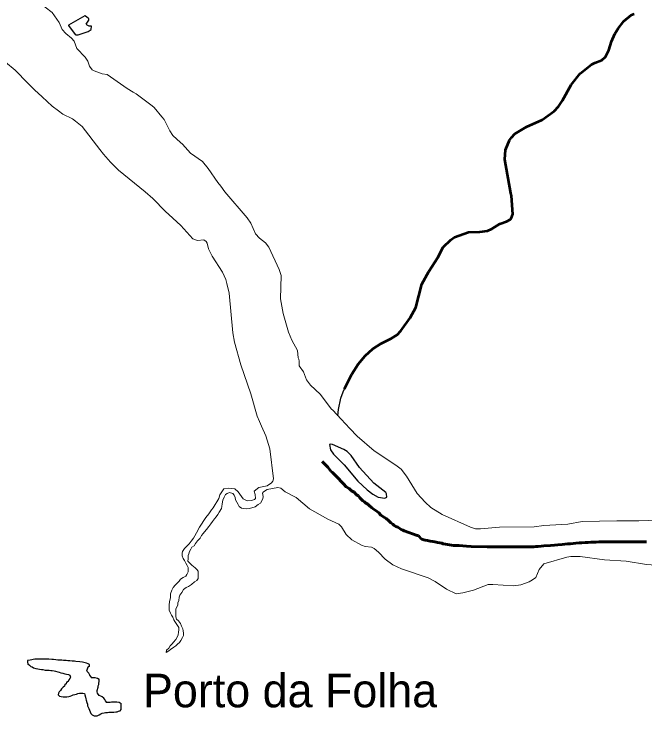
# Model space of a CAD drawing. Extents: x 553962 to 842807, y 8883888 to 9032388.
# Drawn here: x 687800 to 697207, y 8902740 to 8913202 of the extents above; entities that cross this region are included whole.
import ezdxf

# ---------------------------------------------------------------- set-up
doc = ezdxf.new("R2010")
doc.units = 0
doc.header["$LTSCALE"] = 150
doc.linetypes.add('LONG_DASH_SHORT_DASH', pattern=[9.9, 6, -1.2, 1.5, -1.2])
for name, color, linetype, lineweight in [('21', 7, 'Continuous', 25), ('24', 7, 'Continuous', 25), ('25', 7, 'Continuous', 13), ('7', 7, 'LONG_DASH_SHORT_DASH', 60)]:
    doc.layers.add(name, color=color, linetype=linetype, lineweight=lineweight)
doc.layers.add('41', color=7, linetype='Continuous')

msp = doc.modelspace()

# ---------------------------------------------------------------- linework, layer by layer
at = {"layer": '21'}
for points in [[(688952.1, 8912988.5), (688957.2, 8913006.4), (688955.3, 8913022.8), (688921.9, 8913021.5), (688891.5, 8913035.1), (688877.6, 8913051.6), (688914.9, 8913110.7), (688913.3, 8913132.5), (688882.7, 8913161.5), (688854.3, 8913175), (688614.4, 8913034.8), (688610.3, 8913030.2)], [(688610.3, 8913030.2), (688713.4, 8912897.3), (688723.3, 8912892.5), (688740.8, 8912891.2)], [(688740.8, 8912891.2), (688757.5, 8912889.9), (688903.4, 8912939.7), (688947.9, 8912973.7), (688952.1, 8912988.5)], [(688867.2, 8903019), (688872.3, 8902996), (688877.4, 8902975.5), (688885, 8902939.7), (688895.2, 8902914.2), (688895.2, 8902893.7), (688905.4, 8902873.3), (688915.6, 8902852.8), (688923.2, 8902827.3), (688933.4, 8902804.3), (688943.6, 8902778.7), (688964, 8902755.7), (688994.5, 8902742.9), (689017.4, 8902740.4), (689037.8, 8902740.4), (689068.3, 8902758.3), (689093.7, 8902773.6), (689116.6, 8902783.8), (689142.1, 8902788.9), (689165, 8902791.5), (689193, 8902794.1), (689213.3, 8902796.6), (689243.8, 8902799.2), (689266.8, 8902799.2), (689287.1, 8902799.2), (689317.6, 8902801.7), (689338, 8902804.3), (689358.3, 8902811.9), (689383.8, 8902817.1), (689396.5, 8902837.5), (689396.5, 8902858), (689396.5, 8902886.1), (689396.5, 8902921.9), (689365.9, 8902939.8), (689332.8, 8902944.9), (689307.4, 8902944.9), (689282, 8902944.9), (689254, 8902944.9), (689233.6, 8902942.3), (689208.2, 8902942.3), (689185.3, 8902942.3), (689164.9, 8902965.3), (689154.7, 8902985.8), (689139.5, 8903006.2), (689116.5, 8903024.1), (689093.6, 8903034.3), (689068.2, 8903047.1), (689045.3, 8903077.8), (689037.6, 8903098.2), (689037.6, 8903118.7), (689052.9, 8903167.2), (689055.4, 8903190.2), (689065.6, 8903210.7), (689065.6, 8903231.2), (689068.1, 8903251.6), (689068.1, 8903282.3), (689045.2, 8903300.2), (689009.6, 8903307.8), (688984.1, 8903307.8), (688961.2, 8903307.8), (688943.4, 8903328.3), (688928.1, 8903348.7), (688915.4, 8903376.8), (688895, 8903397.3), (688887.4, 8903420.3), (688895, 8903440.8), (688905.2, 8903471.4), (688925.5, 8903489.3), (688925.5, 8903509.8), (688905.2, 8903517.4), (688882.3, 8903527.7), (688861.9, 8903532.8), (688841.6, 8903537.9), (688818.7, 8903540.4), (688783, 8903545.6), (688722, 8903553.2), (688701.6, 8903555.8), (688666, 8903558.3), (688632.9, 8903560.9), (688602.4, 8903563.4), (688576.9, 8903566), (688556.6, 8903568.6), (688536.2, 8903568.6), (688510.8, 8903571.1), (688490.4, 8903573.7), (688454.8, 8903573.7), (688424.2, 8903578.8), (688386.1, 8903581.3), (688363.2, 8903583.9), (688319.9, 8903586.4), (688281.8, 8903589), (688251.2, 8903589), (688218.1, 8903589), (688197.8, 8903589), (688162.2, 8903589), (688131.6, 8903586.4), (688111.3, 8903586.4), (688085.8, 8903581.3), (688065.5, 8903578.8), (688042.6, 8903573.7), (687999.3, 8903568.5)], [(687999.3, 8903568.5), (687999.3, 8903543), (688007, 8903517.4), (688029.9, 8903499.5), (688050.2, 8903479.1), (688070.6, 8903471.4), (688091, 8903458.6), (688124.1, 8903448.4), (688154.6, 8903440.7), (688177.5, 8903438.2), (688208, 8903433.1), (688230.9, 8903430.5), (688264, 8903425.4), (688286.9, 8903425.4), (688322.5, 8903422.8), (688348, 8903420.3), (688368.3, 8903417.7), (688396.3, 8903412.6), (688416.7, 8903407.5), (688452.3, 8903399.8), (688475.2, 8903392.2), (688495.6, 8903381.9), (688528.6, 8903376.8), (688556.6, 8903366.6), (688584.6, 8903361.5), (688612.6, 8903356.4), (688633, 8903346.2), (688643.2, 8903320.6), (688633, 8903300.2), (688617.7, 8903279.7), (688605, 8903254.2), (688584.7, 8903238.8), (688577.1, 8903218.4), (688556.7, 8903205.6), (688551.6, 8903185.1), (688531.3, 8903167.2), (688508.4, 8903146.8), (688490.6, 8903121.2), (688475.3, 8903098.2), (688462.6, 8903077.8), (688457.5, 8903054.8), (688480.4, 8903036.9), (688500.8, 8903029.2), (688531.3, 8903026.7), (688556.8, 8903026.7), (688587.3, 8903026.7), (688615.3, 8903029.2), (688635.6, 8903034.3), (688663.6, 8903044.5), (688684, 8903054.8), (688706.9, 8903062.4), (688732.3, 8903067.6), (688752.7, 8903075.2), (688775.6, 8903077.8), (688806.1, 8903077.8), (688826.5, 8903077.8), (688849.4, 8903075.2), (688857, 8903054.8), (688867.2, 8903019)]]:
    msp.add_lwpolyline(points, dxfattribs=at)
at = {"layer": '21', "lineweight": 13}
for points in [[(687999.3, 8903568.5), (688042.6, 8903573.7), (688065.5, 8903578.8), (688085.8, 8903581.3), (688111.3, 8903586.4), (688131.6, 8903586.4), (688162.2, 8903589), (688197.8, 8903589), (688218.1, 8903589), (688251.2, 8903589), (688281.8, 8903589), (688319.9, 8903586.4), (688363.2, 8903583.9), (688386.1, 8903581.3), (688424.2, 8903578.8), (688454.8, 8903573.7), (688490.4, 8903573.7), (688510.8, 8903571.1), (688536.2, 8903568.6), (688556.6, 8903568.6), (688576.9, 8903566), (688602.4, 8903563.4), (688632.9, 8903560.9), (688666, 8903558.3), (688701.6, 8903555.8), (688722, 8903553.2), (688783, 8903545.6), (688818.7, 8903540.4), (688841.6, 8903537.9), (688861.9, 8903532.8), (688882.3, 8903527.7), (688905.2, 8903517.4), (688925.5, 8903509.8), (688925.5, 8903489.3), (688905.2, 8903471.4), (688895, 8903440.8), (688887.4, 8903420.3), (688895, 8903397.3), (688915.4, 8903376.8), (688928.1, 8903348.7), (688943.4, 8903328.3), (688961.2, 8903307.8), (688984.1, 8903307.8), (689009.6, 8903307.8), (689045.2, 8903300.2), (689068.1, 8903282.3), (689068.1, 8903251.6), (689065.6, 8903231.2), (689065.6, 8903210.7), (689055.4, 8903190.2), (689052.9, 8903167.2), (689037.6, 8903118.7), (689037.6, 8903098.2), (689045.3, 8903077.8), (689068.2, 8903047.1), (689093.6, 8903034.3), (689116.5, 8903024.1), (689139.5, 8903006.2), (689154.7, 8902985.8), (689164.9, 8902965.3), (689185.3, 8902942.3), (689208.2, 8902942.3), (689233.6, 8902942.3), (689254, 8902944.9), (689282, 8902944.9), (689307.4, 8902944.9), (689332.8, 8902944.9), (689365.9, 8902939.8), (689396.5, 8902921.9), (689396.5, 8902886.1), (689396.5, 8902858), (689396.5, 8902837.5), (689383.8, 8902817.1), (689358.3, 8902811.9), (689338, 8902804.3), (689317.6, 8902801.7), (689287.1, 8902799.2), (689266.8, 8902799.2), (689243.8, 8902799.2), (689213.3, 8902796.6), (689193, 8902794.1), (689165, 8902791.5), (689142.1, 8902788.9), (689116.6, 8902783.8), (689093.7, 8902773.6), (689068.3, 8902758.3), (689037.8, 8902740.4), (689017.4, 8902740.4), (688994.5, 8902742.9), (688964, 8902755.7), (688943.6, 8902778.7), (688933.4, 8902804.3), (688923.2, 8902827.3), (688915.6, 8902852.8), (688905.4, 8902873.3), (688895.2, 8902893.7), (688895.2, 8902914.2), (688885, 8902939.7), (688877.4, 8902975.5), (688872.3, 8902996), (688867.2, 8903019)], [(688867.2, 8903019), (688857, 8903054.8), (688849.4, 8903075.2), (688826.5, 8903077.8), (688806.1, 8903077.8), (688775.6, 8903077.8), (688752.7, 8903075.2), (688732.3, 8903067.6), (688706.9, 8903062.4), (688684, 8903054.8), (688663.6, 8903044.5), (688635.6, 8903034.3), (688615.3, 8903029.2), (688587.3, 8903026.7), (688556.8, 8903026.7), (688531.3, 8903026.7), (688500.8, 8903029.2), (688480.4, 8903036.9), (688457.5, 8903054.8), (688462.6, 8903077.8), (688475.3, 8903098.2), (688490.6, 8903121.2), (688508.4, 8903146.8), (688531.3, 8903167.2), (688551.6, 8903185.1), (688556.7, 8903205.6), (688577.1, 8903218.4), (688584.7, 8903238.8), (688605, 8903254.2), (688617.7, 8903279.7), (688633, 8903300.2), (688643.2, 8903320.6), (688633, 8903346.2), (688612.6, 8903356.4), (688584.6, 8903361.5), (688556.6, 8903366.6), (688528.6, 8903376.8), (688495.6, 8903381.9), (688475.2, 8903392.2), (688452.3, 8903399.8), (688416.7, 8903407.5), (688396.3, 8903412.6), (688368.3, 8903417.7), (688348, 8903420.3), (688322.5, 8903422.8), (688286.9, 8903425.4), (688264, 8903425.4), (688230.9, 8903430.5), (688208, 8903433.1), (688177.5, 8903438.2), (688154.6, 8903440.7), (688124.1, 8903448.4), (688091, 8903458.6), (688070.6, 8903471.4), (688050.2, 8903479.1), (688029.9, 8903499.5), (688007, 8903517.4), (687999.3, 8903543), (687999.3, 8903568.5)]]:
    msp.add_lwpolyline(points, dxfattribs=at)
at = {"layer": '24', "lineweight": 53}
for points in [[(695208.7, 8910534.7), (695119.1, 8911032.8), (695125.9, 8911175.9), (695186, 8911322.3), (695215, 8911364.1), (695265.4, 8911414.9), (695441.6, 8911520.3), (695675, 8911623.5), (695855.8, 8911754), (695917.1, 8911825.5), (695978.8, 8911914.3), (696107.7, 8912146.4), (696241.4, 8912314.4), (696408, 8912448.3), (696458.2, 8912475.5), (696564.9, 8912514.1), (696620.1, 8912562.5), (696669.6, 8912662.3), (696705.8, 8912792.2), (696757.7, 8912906), (696806.1, 8912989), (696891.2, 8913095.4), (697004, 8913188.5), (697047.8, 8913204.1)], [(692729.3, 8907617.7), (692837, 8907833), (692931.9, 8907984.6), (693036.8, 8908107.6), (693151.9, 8908211.5), (693272.4, 8908290), (693424.2, 8908367.8), (693510.8, 8908421.2), (693567.8, 8908481.1), (693707.6, 8908675), (693789, 8908827.4), (693880.7, 8909177.6), (693984.3, 8909363.3), (694118.8, 8909572.9), (694196.2, 8909725.9), (694310.5, 8909836.8), (694368.1, 8909876.1), (694574.8, 8909952.9), (694743.6, 8909954), (694858.1, 8909968.9), (694926.1, 8910000.5), (695042.3, 8910075.9), (695142.1, 8910109.8), (695197.6, 8910138.8), (695213.4, 8910155.1), (695235.8, 8910220.2), (695216.8, 8910490.1), (695208.7, 8910534.7)]]:
    msp.add_lwpolyline(points, dxfattribs=at)
at = {"layer": '24'}
for points in [[(695208.7, 8910534.7), (695119.1, 8911032.8), (695125.9, 8911175.9), (695186, 8911322.3), (695215, 8911364.1), (695265.4, 8911414.9), (695441.6, 8911520.3), (695675, 8911623.5), (695855.8, 8911754), (695917.1, 8911825.5), (695978.8, 8911914.3), (696107.7, 8912146.4), (696241.4, 8912314.4), (696408, 8912448.3), (696458.2, 8912475.5), (696564.9, 8912514.1), (696620.1, 8912562.5), (696669.6, 8912662.3), (696705.8, 8912792.2), (696757.7, 8912906), (696806.1, 8912989), (696891.2, 8913095.4), (697004, 8913188.5), (697047.8, 8913204.1)], [(692627.4, 8907216), (692639.9, 8907309.9), (692674.3, 8907477.3), (692707.2, 8907573.5), (692837, 8907833), (692931.9, 8907984.6), (693036.8, 8908107.6), (693151.9, 8908211.5), (693272.4, 8908290), (693424.2, 8908367.8), (693510.8, 8908421.2), (693567.8, 8908481.1), (693707.6, 8908675), (693789, 8908827.4), (693880.7, 8909177.6), (693984.3, 8909363.3), (694118.8, 8909572.9), (694196.2, 8909725.9), (694310.5, 8909836.8), (694368.1, 8909876.1), (694574.8, 8909952.9), (694743.6, 8909954), (694858.1, 8909968.9), (694926.1, 8910000.5), (695042.3, 8910075.9), (695142.1, 8910109.8), (695197.6, 8910138.8), (695213.4, 8910155.1), (695235.8, 8910220.2), (695216.8, 8910490.1), (695208.7, 8910534.7)]]:
    msp.add_lwpolyline(points, dxfattribs=at)
msp.add_lwpolyline([(692949.1, 8906444.8), (692825.9, 8906621.7), (692768.5, 8906681.2), (692716.6, 8906713.2), (692549.3, 8906785.2), (692516.7, 8906791.5), (692502.1, 8906785.4), (692518.4, 8906705.4), (692562.6, 8906642), (692720.7, 8906481.3), (692924.1, 8906239.9), (693063.6, 8906110.7), (693147.4, 8906045), (693227.3, 8906002.2), (693327.7, 8905986.2), (693357, 8906001.2), (693353.1, 8906048.7), (693342.8, 8906070), (693166.4, 8906209.1)], close=True, dxfattribs=at)
at = {"layer": '25'}
for points in [[(687815.5, 8913739.4), (687934.6, 8913642.4), (688040, 8913510.4), (688162, 8913385.5), (688367.3, 8913223), (688472.6, 8913075.7)], [(688472.6, 8913075.7), (688515.8, 8912970.7), (688572.7, 8912913.1), (688657.8, 8912844.4), (688698.2, 8912796.3), (688734.3, 8912690.1), (688862.3, 8912558.1)], [(688862.3, 8912558.1), (688898.2, 8912498.6), (688924.9, 8912425.2), (688966.9, 8912371.6), (688993.2, 8912354.7), (689114.6, 8912309.7), (689186.8, 8912301.9), (689186.9, 8912301.9)], [(688008.3, 8912172.8), (687817.2, 8912367.8), (687672.6, 8912486.6)], [(689186.8, 8912301.9), (689489.2, 8912093.8), (689578.8, 8912037.9)], [(688219.6, 8911966.8), (688106.6, 8912072.5), (688008.3, 8912172.8)], [(689578.8, 8912037.9), (689622.7, 8912010.6), (689858, 8911832.1)], [(688463.8, 8911759.3), (688367.3, 8911828.6), (688219.6, 8911966.8)], [(689858, 8911832.1), (689891.4, 8911806.7), (690003.7, 8911671.2)], [(688717.8, 8911603.4), (688671.3, 8911641.2), (688529.4, 8911712.2), (688463.8, 8911759.3)], [(689135.5, 8911115.7), (689079.9, 8911181.4), (688815.4, 8911524.1), (688717.8, 8911603.4)], [(690003.7, 8911671.2), (690036.2, 8911631.9), (690124.3, 8911459.3), (690170.1, 8911393.1), (690282.6, 8911287.6)], [(690282.6, 8911287.6), (690310.1, 8911261.8), (690430.8, 8911126.3), (690608.8, 8911006.4), (690695.1, 8910901.9), (690838.4, 8910691.9), (690884, 8910634.6)], [(689754.4, 8910550.3), (689356.4, 8910876.9), (689236.6, 8910995.9), (689135.5, 8911115.7)], [(690105.8, 8910215.6), (690059.9, 8910258.2), (689871, 8910454.6), (689754.4, 8910550.3)], [(690884, 8910634.6), (690943.9, 8910550.7), (691277.7, 8910162.7), (691329, 8910084.3), (691401.2, 8909927.1), (691461.9, 8909862.4), (691549.6, 8909789.6), (691600.1, 8909727.4), (691754.7, 8909393.1), (691782, 8909306.7), (691774.2, 8908959.6), (691815.3, 8908738.4), (691889.9, 8908460.7), (691941, 8908340.7), (692026.3, 8908188.9), (692038.9, 8908078.6), (692044.8, 8908056.7)], [(690973.8, 8909186.5), (690959.4, 8909246.9), (690907.6, 8909357.3), (690755.8, 8909591), (690701.9, 8909701.7), (690681.3, 8909786.2), (690666.4, 8909810.3), (690629.5, 8909837.9), (690534.7, 8909826.2), (690465.2, 8909853.3), (690285, 8910049.6), (690105.8, 8910215.6)], [(691088.5, 8908313.9), (691062.8, 8908449.1), (691008.4, 8909041.9), (690973.8, 8909186.5)], [(691281.4, 8907685.4), (691182.4, 8907975.5), (691088.5, 8908313.9)], [(692044.8, 8908056.7), (692052.8, 8908026.7), (692050.7, 8907961), (692118.3, 8907868.3), (692160.1, 8907748.4), (692220.3, 8907669.3), (692364.9, 8907535.6), (692534.1, 8907312.8), (692551.5, 8907299.7), (692676.4, 8907162.1)], [(691462.3, 8907129.9), (691427, 8907209), (691331.2, 8907539.4), (691281.4, 8907685.4)], [(690770.2, 8905843.2), (690852, 8905982.1), (690868.1, 8906034.4), (690928, 8906123.4), (690992.1, 8906133.5), (691093.1, 8906124.6), (691142.8, 8906079.2), (691216.8, 8905979), (691277.6, 8905948.2), (691342.5, 8905951.8), (691386.5, 8905966.2), (691399.8, 8905981.8), (691397.7, 8906042.2), (691378.7, 8906092.7), (691448.3, 8906144.9), (691574.6, 8906171.9), (691637.5, 8906214.2), (691659.8, 8906239.5), (691666.5, 8906276.9), (691614.3, 8906720.4), (691553.2, 8906917.7), (691488.1, 8907058.8), (691462.3, 8907129.9)], [(692676.4, 8907162.1), (692807.4, 8907022.5), (692915.7, 8906912.1), (693169.8, 8906693.4), (693492.8, 8906479), (693569.9, 8906419.6), (693650.4, 8906314.4), (693809.1, 8906055.6), (693809.1, 8906055.6), (693928.4, 8905925.4), (694016.8, 8905845.3), (694182.1, 8905744), (694607.4, 8905554.6), (694682.1, 8905531.8), (694755.6, 8905527.6), (695038, 8905553.4), (695553.9, 8905557.9), (695698.2, 8905581.4), (696059.6, 8905599.2), (696272.7, 8905636.6), (696786.4, 8905651), (697116.6, 8905647.9), (697567.1, 8905664.3)], [(691259.2, 8905826.4), (691259.2, 8905826.4), (691190.1, 8905839.8), (691158.9, 8905862.1), (691141.1, 8905891), (691121, 8905926.7), (691103.2, 8905962.3), (691098.7, 8905998), (691080.9, 8906031.4), (691063.1, 8906058.1), (691014, 8906069.2), (691014, 8906069.2), (690976.2, 8906058.1), (690976.2, 8906058.1), (690950.8, 8906042.4), (690932.7, 8905999.2), (690914.6, 8905958.6), (690901.5, 8905902.7), (690898.7, 8905862), (690893.5, 8905831.5), (690857.5, 8905778.3), (690836.9, 8905745.3), (690816.3, 8905709.8), (690790.7, 8905676.9), (690759.9, 8905638.9), (690736.8, 8905603.4), (690706, 8905562.8), (690670.1, 8905517.2), (690641.9, 8905486.9), (690618.8, 8905459), (690595.7, 8905428.6), (690575.1, 8905388), (690536.7, 8905350.1), (690503.4, 8905312.1), (690485.4, 8905276.6), (690449.6, 8905256.4), (690436.7, 8905228.5), (690418.7, 8905190.4), (690405.7, 8905157.4), (690397.9, 8905129.5), (690397.6, 8905081.1), (690392.3, 8905048.1), (690422.7, 8905017.4), (690453, 8904989.3), (690498.6, 8904945.8), (690526.4, 8904922.7), (690546.6, 8904897.2), (690546.1, 8904820.8), (690543.3, 8904787.8), (690525.4, 8904759.9), (690492.1, 8904737.2), (690446.1, 8904699.3), (690400.1, 8904671.6), (690366.9, 8904653.9), (690328.6, 8904623.6), (690300.3, 8904580.5), (690274.6, 8904539.9), (690261.7, 8904512), (690258.8, 8904461.2), (690240.8, 8904428.2), (690240.6, 8904397.7), (690232.8, 8904369.7), (690214.8, 8904339.3), (690214.6, 8904308.8), (690211.8, 8904260.4), (690211.5, 8904219.8), (690221.5, 8904181.5), (690251.8, 8904155.9), (690282.1, 8904117.6), (690297.2, 8904079.4), (690317.2, 8904038.6), (690319.6, 8904010.6), (690327, 8903972.4), (690326.8, 8903941.8), (690311.3, 8903908.9), (690288.2, 8903863.2), (690267.6, 8903835.3), (690239.5, 8903812.6), (690211.3, 8903787.3), (690183.2, 8903767.1), (690134.7, 8903731.8), (690106.5, 8903709), (690068.2, 8903683.8), (690073.5, 8903719.4), (690106.8, 8903752.2), (690129.9, 8903787.7), (690155.5, 8903813), (690176.1, 8903840.9), (690211.9, 8903881.4), (690230, 8903916.9), (690248, 8903947.4), (690250.8, 8903988), (690256.1, 8904026.2), (690256.3, 8904059.2), (690236.2, 8904089.9), (690218.5, 8904118), (690195.8, 8904146.1), (690180.7, 8904174.1), (690165.7, 8904212.4), (690148.1, 8904243), (690133, 8904273.6)], [(691574.8, 8906114.8), (691519.4, 8906081.7), (691502.8, 8906063.3), (691513.3, 8906012.8), (691511.5, 8905978.9), (691473.5, 8905914.1), (691441.2, 8905891.3)], [(694392.3, 8904560.9), (694249.3, 8904629.2), (694079.7, 8904743.6), (693976.2, 8904798), (693575.7, 8904930.8), (693449.1, 8904994.9), (693335.6, 8905079), (693236.3, 8905180.3), (693168.5, 8905236.3), (693127.6, 8905254.1), (693035.4, 8905267.9), (692983.1, 8905283.9), (692837.7, 8905367.1), (692753.6, 8905443.3), (692681.2, 8905561), (692642.1, 8905601), (692477.9, 8905674), (692207.4, 8905825.7), (692006.3, 8905995.8), (691843, 8906078.6), (691777.9, 8906135.4), (691733.2, 8906147.2), (691574.8, 8906114.8)], [(690133, 8904273.6), (690112.9, 8904319.5), (690113.4, 8904393.3), (690118.8, 8904446.7), (690131.9, 8904502.6), (690134.8, 8904558.5), (690153, 8904614.4), (690171, 8904655), (690204.3, 8904690.4), (690235.1, 8904723.3), (690260.7, 8904751.2), (690283.8, 8904779), (690322.1, 8904801.7), (690360.4, 8904821.8), (690378.3, 8904849.7), (690396.4, 8904887.8), (690396.8, 8904953.9), (690381.7, 8904982), (690361.6, 8905017.7), (690341.5, 8905058.6), (690323.9, 8905086.6), (690306.3, 8905127.4), (690306.6, 8905168.1), (690314.4, 8905193.5), (690340.1, 8905236.6), (690373.4, 8905267), (690409.2, 8905307.5), (690440, 8905348), (690475.9, 8905391.1), (690494, 8905426.6), (690519.7, 8905469.7), (690566, 8905556), (690657.5, 8905699.5), (690657.5, 8905699.5), (690702.1, 8905750.7), (690702.1, 8905750.7), (690746.6, 8905810.9), (690770.2, 8905843.2)], [(691441.2, 8905891.3), (691395.3, 8905858.9), (691308.5, 8905834.7), (691259.2, 8905826.4)], [(697658.8, 8904933.3), (697614.4, 8904938.5), (697502.5, 8904976.8), (697230.9, 8904997.9), (696928.2, 8905046.6), (696603.4, 8905069), (696240.1, 8905118.1), (696100.1, 8905116.6), (696040.6, 8905107), (695698.7, 8905008.5), (695631.9, 8904924.3), (695580.3, 8904801.6), (695529.7, 8904770.2)], [(695529.7, 8904770.2), (695479.1, 8904738.8), (695358.2, 8904694.2), (695244.6, 8904680.4), (694936.5, 8904701), (694868.4, 8904699.3), (694652.2, 8904617.7), (694490.8, 8904574.4), (694392.3, 8904560.9)]]:
    msp.add_lwpolyline(points, dxfattribs=at)
msp.add_lwpolyline([(692949.1, 8906444.8), (692825.9, 8906621.7), (692768.5, 8906681.2), (692716.6, 8906713.2), (692549.3, 8906785.2), (692516.7, 8906791.5), (692502.1, 8906785.4), (692518.4, 8906705.4), (692562.6, 8906642), (692720.7, 8906481.3), (692924.1, 8906239.9), (693063.6, 8906110.7), (693147.4, 8906045), (693227.3, 8906002.2), (693327.7, 8905986.2), (693357, 8906001.2), (693353.1, 8906048.7), (693342.8, 8906070), (693166.4, 8906209.1)], close=True, dxfattribs=at)
at = {"layer": '7'}
for points in [[(693130.7, 8905846.2), (693095, 8905876.9), (693074.7, 8905894.8), (693044.1, 8905912.6), (693023.8, 8905933.1), (693000.9, 8905948.4), (692983.1, 8905968.9), (692955.1, 8905989.3), (692934.7, 8906022.6), (692904.1, 8906037.9), (692871.1, 8906073.7), (692830.3, 8906094.1), (692797.2, 8906132.5), (692754, 8906155.5), (692713.2, 8906198.9), (692680.2, 8906229.6), (692634.3, 8906283.3), (692593.6, 8906324.2), (692550.3, 8906370.2), (692522.3, 8906390.6), (692509.6, 8906411.1), (692476.5, 8906446.9), (692448.5, 8906480.1), (692412.9, 8906510.8), (692392.5, 8906531.2)], [(694492.2, 8905273.6), (694436.2, 8905278.7), (694392.9, 8905278.7), (694352.2, 8905281.3), (694260.6, 8905294.1), (694235.2, 8905299.2), (694197, 8905306.9), (694176.7, 8905314.5), (694151.2, 8905319.6), (694115.6, 8905327.3), (694074.9, 8905335), (694044.3, 8905340.1), (694003.6, 8905347.8), (693965.4, 8905355.4), (693932.4, 8905360.5), (693912, 8905363.1), (693881.5, 8905373.3), (693861.1, 8905391.2), (693830.6, 8905429.6), (693810.2, 8905432.1), (693619.3, 8905498.6), (693596.4, 8905508.8), (693573.5, 8905521.6), (693553.2, 8905534.3), (693522.6, 8905552.2), (693494.6, 8905562.5), (693466.6, 8905580.3), (693448.8, 8905600.8), (693418.3, 8905618.7), (693382.7, 8905654.5), (693349.6, 8905685.2), (693324.1, 8905700.5), (693270.7, 8905733.7), (693240.1, 8905766.9), (693212.1, 8905787.4), (693153.6, 8905828.3), (693130.7, 8905846.2)], [(697230, 8905335), (697186.8, 8905335), (697148.6, 8905335), (697105.3, 8905335), (697082.4, 8905335), (697046.8, 8905335), (697011.2, 8905335), (696990.8, 8905335), (696957.7, 8905335), (696934.8, 8905335), (696896.7, 8905335), (696876.3, 8905335), (696820.3, 8905335), (696772, 8905335), (696721.1, 8905335), (696670.2, 8905335), (696624.4, 8905335), (696578.6, 8905335), (696520.1, 8905335), (696481.9, 8905332.5), (696438.7, 8905332.5), (696398, 8905329.9), (696359.8, 8905327.3), (696314, 8905324.8), (696265.7, 8905322.2), (696227.5, 8905319.7), (696176.6, 8905317.1), (696135.9, 8905312), (696095.2, 8905306.9), (696054.5, 8905304.3), (696013.8, 8905299.2), (695970.5, 8905294.1), (695906.9, 8905289), (695858.6, 8905283.9), (695800, 8905281.3), (695698.3, 8905273.7), (695657.6, 8905271.1), (695616.8, 8905268.5), (695578.7, 8905268.5), (695548.1, 8905263.4), (695510, 8905260.9), (695464.2, 8905260.9), (695426, 8905260.9), (695377.7, 8905260.9), (695339.5, 8905260.9), (695293.7, 8905260.9), (695242.8, 8905260.9), (695194.5, 8905260.9), (695143.6, 8905260.9), (695097.8, 8905260.9), (695052, 8905260.9), (695001.1, 8905260.9), (694945.1, 8905260.9), (694856, 8905263.4), (694614.3, 8905268.5), (694545.6, 8905271.1), (694492.2, 8905273.6)]]:
    msp.add_lwpolyline(points, dxfattribs=at)

# ---------------------------------------------------------------- texts
at = {"layer": '41'}
msp.add_text('Porto da Folha', height=500, dxfattribs=at).set_placement((689722.9, 8902870))

doc.saveas('drawing.dxf')
